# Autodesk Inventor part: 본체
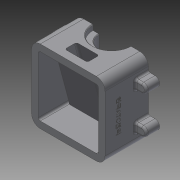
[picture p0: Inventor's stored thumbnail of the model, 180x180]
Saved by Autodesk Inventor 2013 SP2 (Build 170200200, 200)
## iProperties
Created: 2022-03
Part Number: 본체
Material: Generic
Document SubType Name: Modeling
Designer: a
Density: 1 g/cm^3
Author: a
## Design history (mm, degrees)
sketch "스케치1"
  geometry: L1 (-55, -55)-(55, -55); L2 (55, -55)-(55, 55); L3 (55, 55)-(-55, 55); L4 (-55, 55)-(-55, -55); L5 (-55, -55)-(55, 55); L6 (55, -55)-(-55, 55); 1 further point
  constraints: 12 end point, 2 midpoint, 2 parallel, 1 horizontal, 1 perpendicular
  dimensions: "d0" = 110 distance of L2.end L3.end; "d2" = 110 distance of L3.end L1.start
extrude "돌출1" new body sketch "스케치1" distance "d3" = 65; taper "d4" = 0 deg
sketch "스케치3"
  geometry: L1 (55, 55)-(-55, 55) reference; L2 (-55, 55)-(-55, -55) reference; L3 (-55, -55)-(55, -55) reference; L4 (55, -55)-(55, 55) reference; L5 (-45, -45)-(-45, 45); L6 (-45, 45)-(45, 45); L7 (45, 45)-(45, -45); L8 (45, -45)-(30, -45); L9 (30, -45)-(30, 33); L10 (30, 33)-(-30, 33); L11 (-30, 33)-(-30, -45); L12 (-30, -45)-(-45, -45); 2 further points
  constraints: 16 end point, 7 parallel, 1 midpoint, 1 perpendicular, 1 vertical alignment
  dimensions: "d16" = 10 distance between parallel lines of L4 L7; "d17" = 25 distance between parallel lines of L4 L9; "d18" = 25 distance between parallel lines of L2 L11; "d19" = 10 distance between parallel lines of L1 L6; "d20" = 10 distance between parallel lines of L3 L12; "d21" = 10 distance between parallel lines of L3 L8; "d23" = 22 distance between parallel lines of L1 L10
extrude "돌출2" cut sketch "스케치3" stored distance "d24" = 65; taper "d25" = 0 deg
fillet "모깎기1" dims "d26" = 13
sketch "스케치4"
  geometry: L1 (-55, 42)-(-55, -42) reference; L2 (42, 55)-(-42, 55) reference; L3 (-65, 35)-(-55, 35); L4 (-65, 21)-(-55, 21); L5 (-55, 35)-(-55, 21); L6 (-65, -21)-(-55, -21); L7 (-65, -35)-(-55, -35); L8 (-55, -21)-(-55, -35); A1 r 7 centre (-65, 28) between (-65, 35) and (-65, 21); A2 r 7 centre (-65, -28) between (-65, -21) and (-65, -35); 1 further point
  constraints: 12 end point, 4 point on circle, 4 point on line, 4 tangent, 2 centre point, 2 parallel, 2 perpendicular, 1 collinear
  dimensions: "d27" = 65 horizontal distance of point (0, 0) A1.centre; "d28" = 14 diameter of A1; "d29" = 27 distance from line of L2 A1.centre; "d30" = 14 diameter of A2; "d31" = 65 horizontal distance of point (0, 0) A2.centre; "d32" = 56 distance of A2.centre A1.centre
extrude "돌출3" join sketch "스케치4" distance "d33" = 20; taper "d34" = 0 deg
hole "구멍1" diameter "d37" = 3.242; stored, may be unused: countersink angle "d41" = 90 deg, drill point angle "d43" = 118 deg; dims "d35" = 10, "d36" = 10, "d38" = 9, "d39" = 4, "d40" = 2, "d42" = 11
hole "구멍2" diameter "d46" = 3.242; stored, may be unused: countersink angle "d50" = 90 deg, drill point angle "d52" = 118 deg; dims "d44" = 10, "d45" = 10, "d47" = 9, "d48" = 4, "d49" = 2, "d51" = 11
sketch "스케치7"
  geometry: L1 (37, 55)-(37, 47); L2 (37, 47)-(46, 47); L3 (46, 47)-(46, -25); L4 (46, -25)-(65, -25); L5 (37, 55)-(65, 55); L6 (65, -25)-(65, 55); 2 further points
  constraints: 12 end point, 2 perpendicular, 2 vertical, 1 parallel, 1 point on line
  dimensions: "d55" = 8 distance of L1.start L1.end; "d57" = 72 distance between parallel lines of L4 L2; "d60" = 38 diameter of L3 L6; "d61" = 56 diameter of L1 L6
revolve "회전1" sketch "스케치7" stored, may be unused: angle "d62" = 90 deg
sketch "스케치8" dims "d63" = 46
  geometry: A1 r 28 centre (0, 0) between (-28, 0) and (28, 0) reference; A2 r 19 centre (0, 0) between (-19, 0) and (19, 0) reference; 3 further points
  constraints: 2 vertical alignment, 1 coincident, 2 other
hole "구멍3" sketch "스케치8" at (0, -23) diameter "d64" = 3.242; stored, may be unused: countersink angle "d68" = 90 deg, drill point angle "d70" = 118 deg; dims "d65" = 9, "d66" = 4, "d67" = 2, "d69" = 11
sketch "스케치9"
  geometry: L1 (65, -19)-(65, 19); L2 (65, 19)-(38.843, 19); L3 (38.843, 19)-(29.197, 55); L4 (29.197, 55)-(11.597, 55); L5 (11.597, 55)-(31.425, -19); L6 (31.425, -19)-(65, -19); L7 (65, -25)-(65, 47) reference; L8 (37, 55)-(65, 55) reference; L9 (30, -33)-(7.833, 49.727); L10 (7.833, 49.727)-(0, 49.727); L11 (65, -33)-(0, -33) reference; L12 (30, -33)-(0, -33); L13 (0, -33)-(0, 49.727); L14 (0, -55)-(65, -55) reference; 2 further points
  constraints: 20 end point, 5 parallel, 3 point on line, 2 perpendicular, 1 collinear, 1 midpoint, 1 vertical
  dimensions: "d72" = 75 deg angle of L2 L3; "d73" = 17 distance between parallel lines of L5 L3; "d75" = 38 distance between parallel lines of L2 L6; "d77" = 36 distance between parallel lines of L8 L2; "d78" = 30 distance of L9.start L12.end; "d79" = 5 distance between parallel lines of L5 L9; "d80" = 22 distance between parallel lines of L14 L12; "d81" = 5.273 distance between parallel lines of L4 L10
extrude "돌출4" cut sketch "스케치9" stored distance "d82" = 34; taper "d83" = 0 deg
sketch "스케치10"
  geometry: C1 r 7.5 at (0, 0); A1 r 19 centre (0, 0) between (-19, 0) and (19, 0) reference; 1 further point
  constraints: 1 centre point, 1 coincident
  dimensions: "d84" = 15 diameter of C1
extrude "돌출5" cut sketch "스케치10" distance "d85" = 4; taper "d86" = -30 deg
sketch "스케치11"
  geometry: L1 (30, -33)-(9.1, 45); L2 (9.1, 45)-(0, 45); L3 (30, -33)-(0, -33); L4 (0, -33)-(0, 45); L5 (65, 55)-(0, 55) reference; L6 (11.597, 55)-(31.425, -19) reference; L7 (0, -55)-(65, -55) reference; 1 further point
  constraints: 8 end point, 2 parallel, 1 horizontal, 1 perpendicular, 1 point on line
  dimensions: "d87" = 10 distance between parallel lines of L5 L2; "d89" = 5 distance between parallel lines of L1 L6; "d90" = 22 distance between parallel lines of L7 L3
extrude "돌출6" cut sketch "스케치11" stored distance "d91" = 71.5; taper "d92" = 0 deg
fillet "모깎기2" dims "d93" = 3
fillet "모깎기4" dims "d95" = 3
fillet "모깎기5" dims "d96" = 3
fillet "모깎기6" dims "d97" = 3
fillet "모깎기7" dims "d98" = 3
fillet "모깎기10" dims "d101" = 3
fillet "모깎기11" dims "d102" = 3
fillet "모깎기12" dims "d103" = 3
fillet "모깎기13" dims "d104" = 3
fillet "모깎기14" dims "d105" = 1
chamfer "모따기2" distance "d109" = 1; stored, may be unused: second distance "d110" = 2, angle "d111" = 45 deg
sketch "스케치12"
  geometry: L1 (-13, 65)-(-13, 0) reference; 2 further points
  constraints: 1 other
  dimensions: "d112" = 55 distance from line of L1 point (42, 20); "d113" = 20 distance of point (42, 0) point (42, 20)
feature "엠보싱1" sketch "스케치12" dims "d0" = 110, "d2" = 110, "d16" = 10, "d17" = 25, "d18" = 25, "d19" = 10, "d20" = 10, "d21" = 10, "d23" = 22, "d114" = 0.5, "d115" = 0
node "솔리드1"
mirror "대칭1"
